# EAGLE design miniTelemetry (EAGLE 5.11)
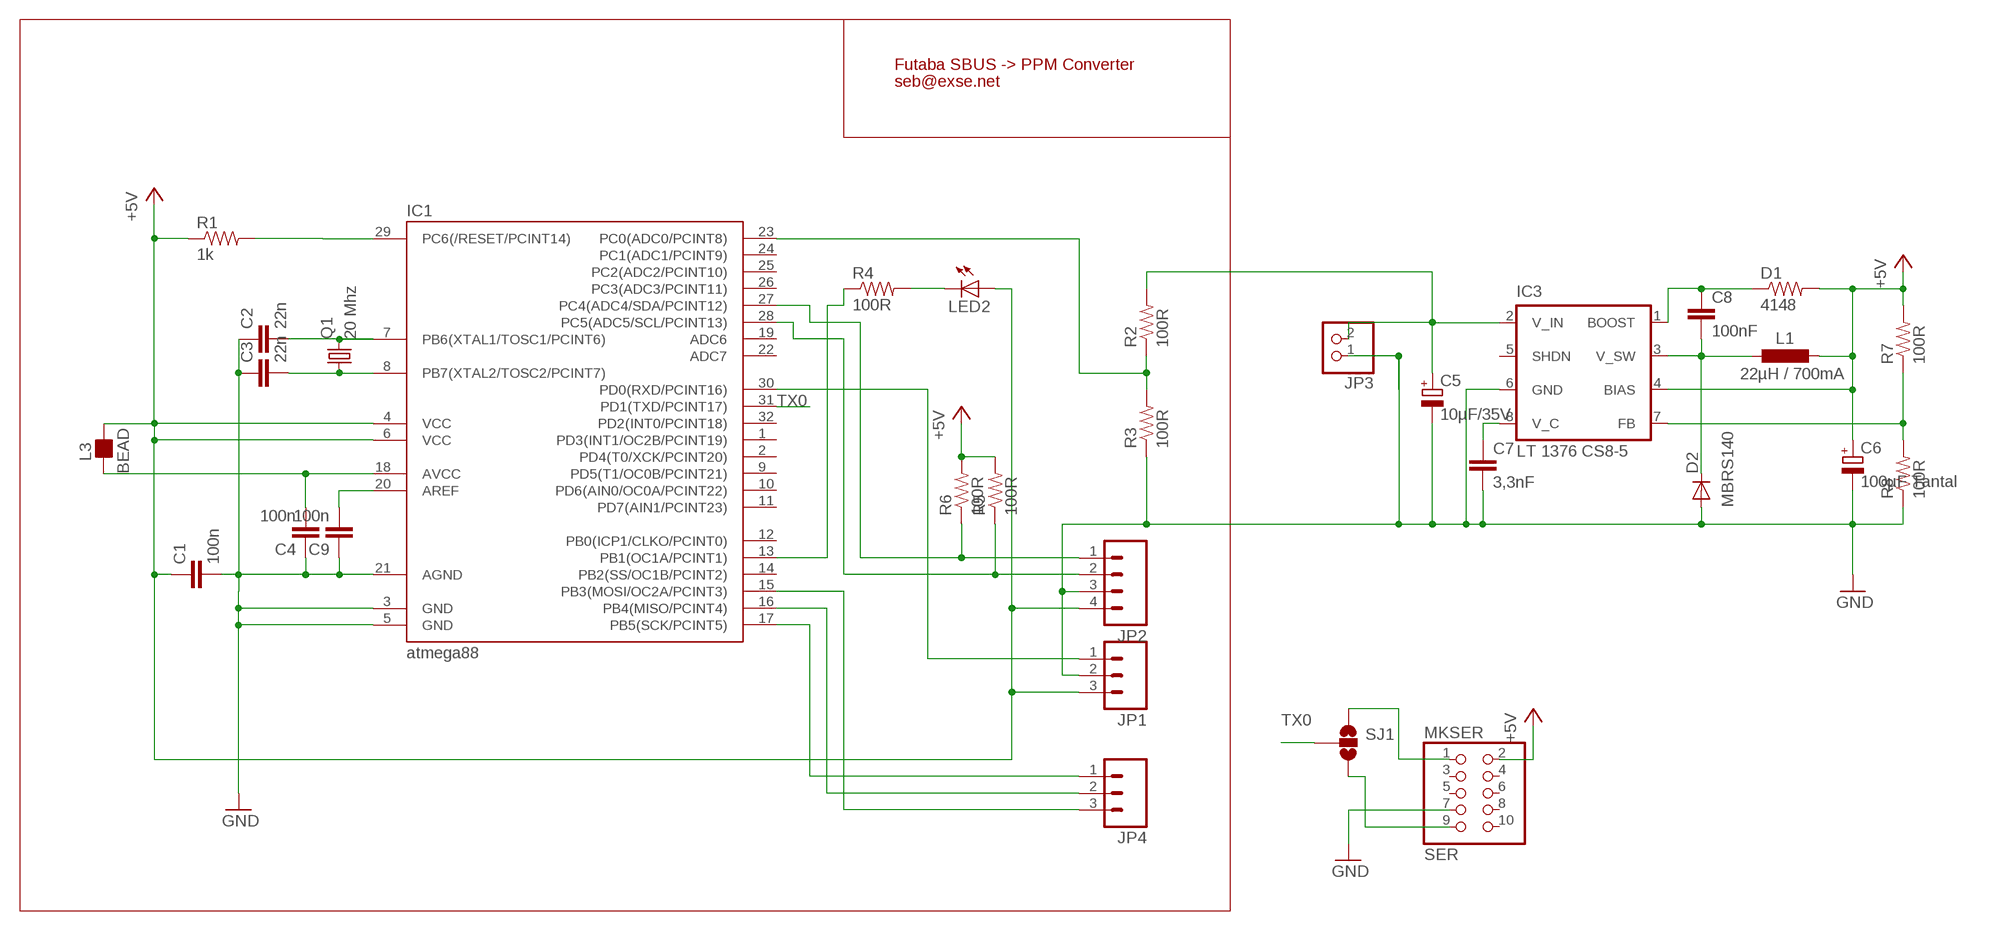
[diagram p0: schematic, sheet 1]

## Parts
C1  100n  CAP0805  [0805]
C2  22n  CAP0805  [0805]
C3  22n  CAP0805  [0805]
C4  100n  CAP0805  [0805]
C5  10µF/35V  CPOL-EUSMCD  [SMC_D]
C6  100µF Tantal  CPOL-EUSMCD  [SMC_D]
C7  3,3nF  CAP0805  [0805]
C8  100nF  CAP0805  [0805]
C9  100n  CAP0805  [0805]
D1  4148  RESISTOR1206  [1206]
D2  MBRS140  DIODE-SMB  [SMB]
IC1  atmega88  MEGA48/88/168-AU  [TQFP32-08]
IC3  LT 1376 CS8-5  LT1376  [SO-08]
JP1  M031X03_NO_SILK  [1X03_NO_SILK]
JP2  M041X04_NO_SILK  [1X04_NO_SILK]
JP3  PINHD-1X02_2.54-90°  [1X02/90]
JP4  M031X03_NO_SILK  [1X03_NO_SILK]
L1  22µH / 700mA  PIS2408  [PIS2408]
L3  BEAD  FB_0805  [L0805]
LED2  LEDCHIPLED_0805  [CHIPLED_0805]
MKSER  SER  PINHD-2X5/90  [2X05/90]
Q1  20 Mhz  CRYSTAL5X3  [CRYSTAL-SMD-5X3]
R1  1k  RESISTOR  [0805]
R2  100R  RESISTOR  [0805]
R3  100R  RESISTOR  [0805]
R4  100R  RESISTOR  [0805]
R5  100R  RESISTOR  [0805]
R6  100R  RESISTOR  [0805]
R7  100R  RESISTOR  [0805]
R8  100R  RESISTOR  [0805]
SJ1  SOLDERJUMPER_2WAYS  [SJ_3]

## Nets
+5V: C1.1 C6.+ D1.2 IC1.4(VCC) IC1.6(VCC) IC3.4(BIAS) JP1.3 JP2.4 L1.P$2 L3.2 LED2.A MKSER.2 R1.1 R5.2 R6.2 R7.2
GND: C1.2 C2.1 C3.1 C4.1 C5.- C6.- C7.2 C9.1 D2.A IC1.3(GND) IC1.5(GND) IC1.21(AGND) IC3.6(GND) JP1.2 JP2.3 JP3.1 MKSER.7 R3.1 R8.1
N$1: IC1.17(PB5(SCK/PCINT5)) JP4.1
N$2: IC1.28(PC5(ADC5/SCL/PCINT13)) JP2.2 R5.1
N$3: IC1.27(PC4(ADC4/SDA/PCINT12)) JP2.1 R6.1
N$4: IC1.23(PC0(ADC0/PCINT8)) R2.1 R3.2
N$5: MKSER.9 SJ1.3
N$6: MKSER.1 SJ1.1
N$7: IC1.16(PB4(MISO/PCINT4)) JP4.2
N$8: IC1.29(PC6(/RESET/PCINT14)) R1.2
N$9: C3.2 IC1.8(PB7(XTAL2/TOSC2/PCINT7)) Q1.1
N$10: C2.2 IC1.7(PB6(XTAL1/TOSC1/PCINT6)) Q1.3
N$11: IC1.15(PB3(MOSI/OC2A/PCINT3)) JP4.3
N$12: IC3.7(FB) R7.1 R8.2
N$13: C4.2 IC1.18(AVCC) L3.1
N$14: LED2.C R4.2
N$15: IC1.13(PB1(OC1A/PCINT1)) R4.1
N$16: C9.2 IC1.20(AREF)
N$41: C5.+ IC3.2(V_IN) JP3.2 R2.2
N$56: C7.1 IC3.8(V_C)
N$57: C8.2 D2.C IC3.3(V_SW) L1.P$1
N$58: C8.1 D1.1 IC3.1(BOOST)
RX0: IC1.30(PD0(RXD/PCINT16)) JP1.1
TX0: IC1.31(PD1(TXD/PCINT17)) SJ1.2
Unconnected: IC1.1(PD3(INT1/OC2B/PCINT19)) IC1.2(PD4(T0/XCK/PCINT20)) IC1.9(PD5(T1/OC0B/PCINT21)) IC1.10(PD6(AIN0/OC0A/PCINT22)) IC1.11(PD7(AIN1/PCINT23)) IC1.12(PB0(ICP1/CLKO/PCINT0)) IC1.14(PB2(SS/OC1B/PCINT2)) IC1.19(ADC6) IC1.22(ADC7) IC1.24(PC1(ADC1/PCINT9)) IC1.25(PC2(ADC2/PCINT10)) IC1.26(PC3(ADC3/PCINT11)) IC1.32(PD2(INT0/PCINT18)) IC3.5(SHDN) MKSER.3 MKSER.4 MKSER.5 MKSER.6 MKSER.8 MKSER.10

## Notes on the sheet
- Futaba SBUS -> PPM Converter
- seb@exse.net

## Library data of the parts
C1-C4 C7-C9 = SparkFun:CAP: Capacitor
C5 C6 = resistor:CPOL-EU: POLARIZED CAPACITOR, European symbol
D1 R1-R8 = SparkFun:RESISTOR: Resistor
D2 = diode:DIODE-: DIODE
IC1 = avr-4:MEGA48/88/168
IC3 = v-reg:LT1376
JP1 JP4 = SparkFun:M03: Header 3 Standard 3-pin 0.1" header. Use with straight break away headers (SKU : PRT-00116), right angle break away headers (PRT-00553), swiss pins (PRT-00743), machine pins (PRT-00117), and female headers (PRT-00115). Molex polarized connector foot print use with SKU : PRT-08232 with associated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
JP2 = SparkFun:M04: Header 4 Standard 4-pin 0.1" header. Use with straight break away headers (SKU : PRT-00116), right angle break away headers (PRT-00553), swiss pins (PRT-00743), machine pins (PRT-00117), and female headers (PRT-00115). Molex polarized connector foot print use with SKU : PRT-08231 with associated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
JP3 = pinhead-2:PINHD-1X02: PIN HEADER
L1 = seb:PIS2408
L3 = rc-master-smd:FB_: FERRITE BEAD
LED2 = led:LED: LED
MKSER = pinhead:PINHD-2X5: PIN HEADER
Q1 = SparkFun:CRYSTAL: Crystals
SJ1 = SparkFun:SOLDERJUMPER_2WAY: Solder Jumper 2 way solder jumper

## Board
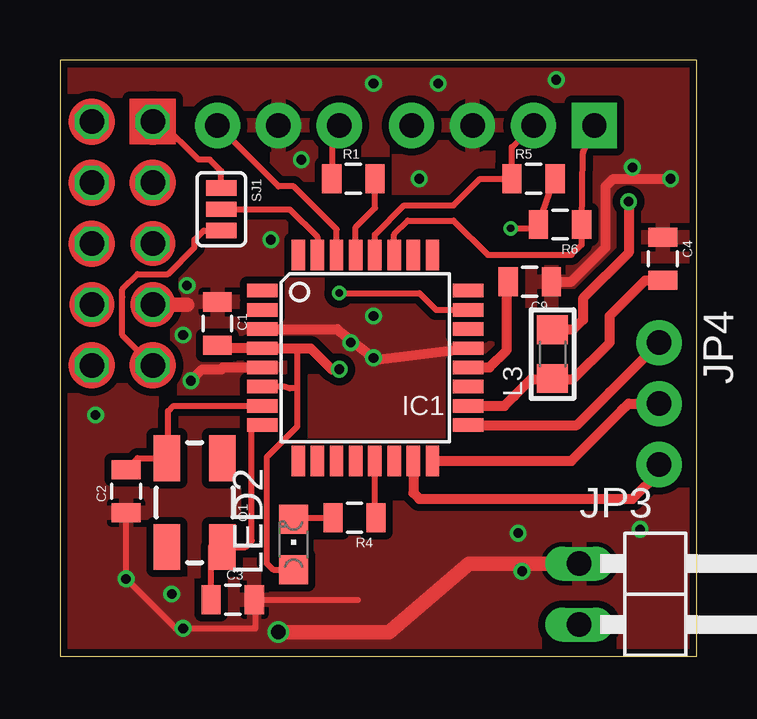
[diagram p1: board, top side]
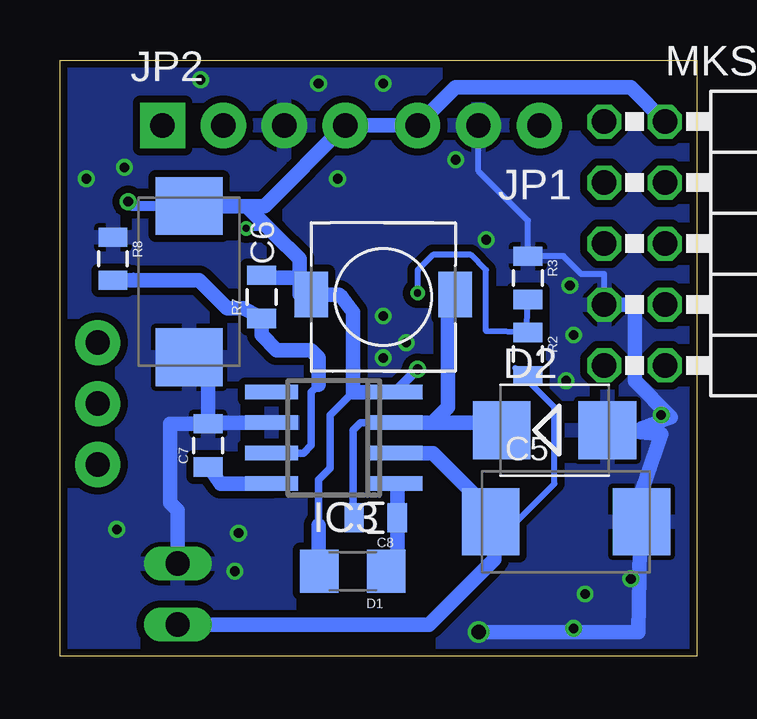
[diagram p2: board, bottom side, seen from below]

Size 26.56 x 24.85 mm. Coordinates in mm from the lower left corner, seen from the top.
Outline: 0,0 26.56,0 26.56,24.85 0,24.85 0,0
Copper layers (1*16): Top 0.035mm / dielectric 1.5mm / Bottom 0.035mm
Design rules "PCB-POOL Standard *": minimum track width 0.15mm, minimum drill 0.3mm, track to track 0.15mm, track to pad 0.15mm, pad to pad 0.15mm, via to via 0.15mm, smd to smd 0.15mm, copper to edge 0.3mm, drill to drill 0.2mm, minimum pad ring 0.2mm, minimum via ring 0.15mm, stop-mask expansion 0.075mm, vias tented up to drill 100mil, thermal gap 0.2mm

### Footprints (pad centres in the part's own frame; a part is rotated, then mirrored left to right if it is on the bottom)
0805 = smd 0.8 x 1.2: 1 -0.9,0; 2 0.9,0
SMC_D = smd 2.4 x 2.8: + -3.15,0; - 3.15,0
1206 = smd 1.6 x 1.8: 1 -1.4,0; 2 1.4,0
SMB = smd 2.4 x 2.4: A 2.2,0; C -2.2,0
TQFP32-08 = smd 1.27 x 0.559: 1 -4.293,2.8; 2 -4.293,2; 3 -4.293,1.2; 4 -4.293,0.4; 5 -4.293,-0.4; 6 -4.293,-1.2; 7 -4.293,-2; 8 -4.293,-2.8; 17 4.293,-2.8; 18 4.293,-2; 19 4.293,-1.2; 20 4.293,-0.4; 21 4.293,0.4; 22 4.293,1.2; 23 4.293,2; 24 4.293,2.8 | smd 0.559 x 1.27: 9 -2.8,-4.293; 10 -2,-4.293; 11 -1.2,-4.293; 12 -0.4,-4.293; 13 0.4,-4.293; 14 1.2,-4.293; 15 2,-4.293; 16 2.8,-4.293; 25 2.8,4.293; 26 2,4.293; 27 1.2,4.293; 28 0.4,4.293; 29 -0.4,4.293; 30 -1.2,4.293; 31 -2,4.293; 32 -2.8,4.293
SO-08 = smd 0.6 x 2.2: 1 -1.905,-2.6; 2 -0.635,-2.6; 3 0.635,-2.6; 4 1.905,-2.6; 5 1.905,2.6; 6 0.635,2.6; 7 -0.635,2.6; 8 -1.905,2.6
1X03_NO_SILK = drill 1.016 pad 1.88 round: 1 0,0; 2 2.54,0; 3 5.08,0
1X04_NO_SILK = drill 1.016 pad 1.88 square: 1 0,0 | drill 1.016 pad 1.88 round: 2 2.54,0; 3 5.08,0; 4 7.62,0
1X02/90 = drill 1.016 long: 1 -2.54,-3.81; 2 0,-3.81
PIS2408 = smd 1.4 x 1.9: P$1 -3,-0.1; P$2 3,-0.1
L0805 = smd 1.2 x 1.3: 1 -1.016,0; 2 1.016,0
CHIPLED_0805 = smd 1.2 x 1.2: A 0,-1.05; C 0,1.05
2X05/90 = drill 1.016 octagon: 1 -5.08,-6.35; 2 -5.08,-3.81; 3 -2.54,-6.35; 4 -2.54,-3.81; 5 0,-6.35; 6 0,-3.81; 7 2.54,-6.35; 8 2.54,-3.81; 9 5.08,-6.35; 10 5.08,-3.81
CRYSTAL-SMD-5X3 = smd 1.9 x 1.1: 1 -1.85,-1.15; 2 1.85,-1.15; 3 1.85,1.15; 4 -1.85,1.15
SJ_3 = smd 0.635 x 1.27: 1 -0.889,0; 2 0,0; 3 0.889,0

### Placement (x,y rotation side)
C1  6.57,13.87 90 top
C2  2.76,6.88 90 top
C3  7.2,2.36 180 top
C4  25.14,16.57 270 top
C5  5.45,5.61 0 bottom
C6  21.17,15.61 270 bottom
C7  20.38,8.79 90 bottom
C8  13.39,5.77 180 bottom
C9  19.58,15.61 180 top
D1  14.34,3.55 180 bottom
D2  5.93,9.42 0 bottom
IC1  12.73,12.44 0 top
IC3  15.14,9.11 90 bottom
JP1  6.57,22.12 180 bottom
JP2  22.28,22.12 0 bottom
JP3  25.46,1.33 270 top
JP4  24.98,13.07 270 top
L1  13.07,14.98 180 bottom
L3  20.54,12.6 90 top
LED2  9.74,4.66 0 top
MKSER  -2.48,17.2 270 bottom
Q1  5.61,6.41 90 top
R1  12.24,19.9 0 top
R2  7.04,12.6 270 bottom
R3  7.04,15.77 270 bottom
R4  12.28,5.77 180 top
R5  19.74,19.9 0 top
R6  20.85,18 180 top
R7  18.15,14.98 90 bottom
R8  24.35,16.57 270 bottom
SJ1  6.72,18.63 270 top

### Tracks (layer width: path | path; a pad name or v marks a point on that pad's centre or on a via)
+5V  (via drill 0.3, 0.4)
  Top 0.254: LED2.A 8.89,3.61 8.63,3.87 8.63,8.31 9.9,9.58 9.9,11.17 | 9.9,11.17 9.58,11.17 9.35,11.24 IC1.6 | IC1.4 9.34,12.84 9.58,12.76 9.9,12.92 9.9,11.17 | R5.2 20.59,19.85 R6.2 19.95,17.84 v18.79,17.84 | R1.1 11.34,21.81 JP1.3
  Top 0.406: v23.71,18.95 23.71,16.82 21.81,14.92 21.81,14.03 21.39,13.61 L3.2 | C1.1 6.69,12.84 IC1.4 10.45,12.84 11.33,11.96 v11.65,11.96
  Bottom 0.254: v18.79,17.84 17.84,17.84 17.6,17.6
  Bottom 0.305: 14.34,11.01 15.3,10.06 15.3,7.84 15.77,7.36 15.77,5.3
  Bottom 0.406: v23.71,18.95 23.53,18.76 C6.+ | IC3.4 12.54,11.07 v11.65,11.96
  Bottom 0.61: D1.2 15.77,3.68 15.77,5.3 15.77,5.45 | IC3.4 14.34,11.01 14.34,14.34 14.82,14.98 14.92,15.08 L1.P$2 16.57,15.1 16.57,15.77 | 16.57,15.77 16.57,16.57 17.6,17.6 18.76,18.76 | 18.76,18.76 C6.+ | JP2.4 18.02,18.76 18.76,18.76 | JP2.4 | JP2.4 JP1.3 10.06,23.71 2.76,23.71 MKSER.2 | R7.2 18.37,15.77 16.57,15.77
GND  (via drill 0.4, 0.6)
  Top 0.254: 12.42,2.36 C3.1 8.15,2.41 8.15,1.17 4.82,1.17 v2.76,3.23 | v2.76,3.23 C2.1 v2.76,3.23
  Top 0.406: C9.1 21.33,15.61 22.76,17.04 22.76,19.58 23.08,19.9 v25.46,19.9 | IC1.21 13.15,12.36 v13.07,12.44 11.56,13.64 IC1.3 | IC1.5 6.8,12.04 6.72,11.96 5.93,11.96 v5.45,11.49
  Top 0.61: MKSER.7 5.3,14.66 | MKSER.7 | v9.11,1.01 13.71,1.01 17.04,3.87 JP3.1
  Bottom 0.254: 2.3,9.5 D2.A 3.42,9.74 3.41,9.74 | 2.36,5.69 2.36,5.67 C5.- 2.3,3.68 v2.76,3.23 | JP1.2 9.11,20.22 7.04,18.15 R3.1 5.56,16.67 4.82,15.93 3.87,15.93 MKSER.7
  Bottom 0.61: 2.28,5.77 2.36,5.69 2.44,1.01 7.68,1.01 v9.11,1.01 | 3.41,9.74 3.07,9.4 1.49,9.26 2.3,6.91 C5.- | 2.3,9.5 1.09,9.97 2.6,11.49 2.6,14.66 MKSER.7 | IC3.6 20.38,9.74 C7.2 | C6.- 20.38,12.46 C7.2 | C7.2 21.96,9.69 21.96,6.41 21.65,6.09 JP3.1
  other vias: 15.77,23.87 1.49,10.06 4.66,2.6 19.27,3.55 20.69,24.03 13.07,23.87 5.3,15.46 12.12,13.07 13.07,14.19 8.79,17.36 23.87,20.38 14.98,19.9 10.06,20.69 24.19,5.3 5.14,1.17 19.11,5.14 5.14,13.39
  pour Top (isolate 0.305): 0.06,24.82 26.57,24.82 26.57,-0.26 0.06,-0.26
  pour Bottom (isolate 0.305): 0.06,24.82 26.57,24.82 26.57,-0.26 0.06,-0.26
N$1
  Top 0.406: IC1.17 21.55,9.64 22.92,11.01 JP4.1 | JP4.1
N$2
  Top 0.254: IC1.28 13.13,17.58 14.34,18.79 16.41,18.79 17.52,19.9 R5.1 18.84,21.22 JP2.2
N$3
  Top 0.254: IC1.27 13.93,17.58 14.5,18.15 16.41,18.15 17.84,16.73 21.01,16.73 21.33,16.73 21.75,17.15 R6.1 21.81,20.96 JP2.1
N$4  (via drill 0.3)
  Top 0.254: IC1.23 15.68,14.44 14.98,15.14 v11.65,15.14 | v11.65,15.14
  Bottom 0.254: v11.65,15.14 11.65,16.09 11.01,16.73 9.42,16.73 8.79,16.09 8.79,13.55 R2.1 7.1,13.82 R3.2
N$5
  Top 0.254: MKSER.9 2.6,13.39 2.6,14.98 2.6,15.3 3.23,15.93 4.5,15.93 5.61,17.04 5.61,17.36 5.99,17.74 SJ1.3
N$6
  Top 0.254: SJ1.1 | SJ1.1 6.72,20.22 6.25,20.69 5.77,20.69 4.18,22.28 MKSER.1
N$7
  Top 0.406: IC1.16 21.32,8.15 23.39,10.22 23.71,10.53 JP4.2
N$8
  Top 0.254: IC1.29 12.33,17.89 12.92,18.47 13.14,18.69 R1.2
N$9
  Top 0.254: IC1.8 7.99,9.51 7.99,4.82 7.73,4.56 Q1.1 6.3,4.57 C3.2
N$10
  Top 0.254: 6.09,10.44 4.72,10.44 4.5,10.22 4.5,9.09 Q1.3 3.23,8.26 C2.2 | 6.09,10.44 IC1.7 | 6.09,10.44
N$11
  Top 0.406: IC1.15 14.73,6.81 14.98,6.57 23.87,6.57 24.98,7.68 24.98,7.84 JP4.3
N$12
  Bottom 0.254: R8.2 23.5,15.88
  Bottom 0.305: IC3.7 16.41,8.47 16.09,8.79 16.09,11.01 15.77,11.33
  Bottom 0.61: R7.1 18.9,14.5 19.58,14.5 20.75,15.67 R8.2 | R7.1 | R7.1 18.15,13.39 17.52,12.76 16.09,12.76 15.77,12.44 15.77,11.33
N$13
  Top 0.406: IC1.18 18.54,10.44 18.95,10.85 19.65,11.55 20.54,11.55 | C4.2 24.4,15.67 22.92,14.19 22.92,13.07 21.39,11.55 20.54,11.55 | 20.54,11.55 L3.1
N$14
  Top 0.254: LED2.C 9.8,5.77 R4.2
N$15
  Top 0.254: R4.1 13.13,6.04 IC1.13
N$16
  Top 0.406: C9.2 18.63,14.77 18.63,12.76 17.91,12.04 IC1.20
N$41
  Bottom 0.254: C5.+ 7.52,5.61 5.93,7.2 5.93,10.38 7.57,12.02 R2.2
  Bottom 0.61: IC3.2 | IC3.2 11.01,8.47 10.69,8.15 8.6,6.06 C5.+ 8.45,4.16 8.45,4.05 11.17,1.33 18.63,1.33 JP3.2
N$56
  Bottom 0.61: IC3.8 19.85,7.2 20.32,7.84 C7.1
N$57
  Bottom 0.305: 14.34,5.98 14.34,7.99 14.34,9.42 14.03,9.74 IC3.3
  Bottom 0.61: L1.P$1 10.38,14.9 10.38,10.38 10.85,9.9 11.01,9.74 | 14.34,5.98 C8.2 | 11.01,9.74 IC3.3 | D2.C 8.45,9.74 11.01,9.74
N$58
  Bottom 0.61: IC3.1 12.49,7.15 C8.1 12.49,4 D1.1
RX0
  Top 0.254: JP1.1 9.11,19.58 9.74,19.58 11.53,17.79 IC1.30
TX0
  Top 0.254: IC1.31 10.73,17.48 9.58,18.63 8.63,18.63 SJ1.2
(copper drawn outside any net)
  shapes: Top area x1, Top circle x10

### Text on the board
tStop: seb@exse.net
